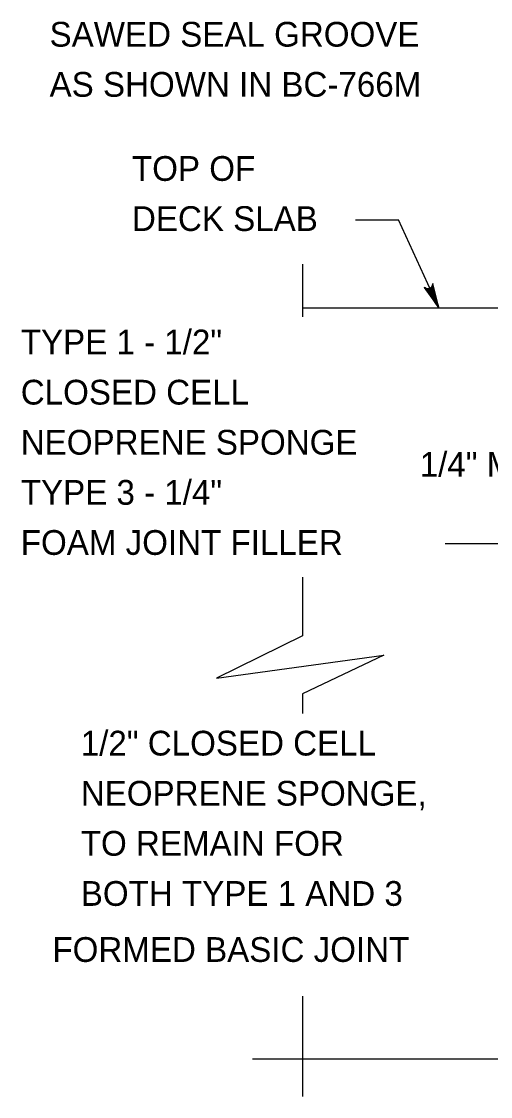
# Model space of a CAD drawing. Extents: x 636530 to 644067, y 294168 to 299122.
# Drawn here: x 636530 to 636586.8, y 298171.3 to 298301.5 of the extents above; entities that cross this region are included whole.
import ezdxf

# ---------------------------------------------------------------- set-up
doc = ezdxf.new("R2010")
doc.units = 0
doc.layers.add('1', color=7, linetype='Continuous')

msp = doc.modelspace()

# ---------------------------------------------------------------- linework, layer by layer
at = {"layer": '1'}
for p, q in [((636570.45, 298277.53), (636575.65, 298277.53)), ((636580.52, 298266.86), (636575.65, 298277.53)), ((636564.03, 298272.15), (636564.03, 298265.78)), ((636564.03, 298266.86), (636611.26, 298266.86)), ((636581.3, 298238.29), (636592.46, 298238.29)), ((636564.03, 298234.23), (636564.03, 298227.12)), ((636564.03, 298227.12), (636553.59, 298222.01)), ((636553.59, 298222.01), (636573.88, 298224.77)), ((636573.88, 298224.77), (636564.03, 298220.08)), ((636564.03, 298220.08), (636564.03, 298217.7)), ((636564.03, 298183.46), (636564.03, 298171.31)), ((636557.95, 298175.87), (636599.25, 298175.87))]:
    msp.add_line(p, q, dxfattribs=at)
msp.add_lwpolyline([(636580.52, 298266.86), (636579.79, 298269.8), (636579.77, 298269.66), (636579.74, 298269.53), (636579.67, 298269.43), (636579.61, 298269.34), (636579.52, 298269.28), (636579.44, 298269.22), (636579.34, 298269.2), (636579.24, 298269.17), (636579.13, 298269.18), (636579.01, 298269.19), (636578.89, 298269.27), (636578.77, 298269.34), (636580.52, 298266.86), (636578.89, 298269.27), (636579.01, 298269.19), (636580.52, 298266.86), (636579.13, 298269.18), (636579.24, 298269.17), (636580.52, 298266.86), (636579.34, 298269.2), (636579.44, 298269.22), (636580.52, 298266.86), (636579.52, 298269.28), (636579.61, 298269.34), (636580.52, 298266.86), (636579.67, 298269.43), (636579.74, 298269.53), (636580.52, 298266.86), (636579.77, 298269.66)], dxfattribs=at)

# ---------------------------------------------------------------- texts
for s, p in [('SAWED SEAL GROOVE', (636533.38, 298298.5)), ('AS SHOWN IN BC-766M', (636533.38, 298292.43)), ('TOP OF', (636543.36, 298282.24)), ('DECK SLAB', (636543.36, 298276.17)), ('TYPE 1 - 1/2"', (636529.89, 298261.22)), ('CLOSED CELL', (636529.89, 298255.14)), ('NEOPRENE SPONGE', (636529.89, 298249.07)), ('1/4" MIN.', (636578.22, 298246.39)), ('TYPE 3 - 1/4"', (636529.89, 298243)), ('FOAM JOINT FILLER', (636529.89, 298236.93)), ('1/2" CLOSED CELL', (636537.16, 298212.62)), ('NEOPRENE SPONGE,', (636537.16, 298206.55)), ('TO REMAIN FOR', (636537.16, 298200.48)), ('BOTH TYPE 1 AND 3 ', (636537.16, 298194.41)), ('FORMED BASIC JOINT', (636533.72, 298187.62))]:
    msp.add_text(s, height=3, dxfattribs=at).set_placement(p)

doc.saveas('drawing.dxf')
